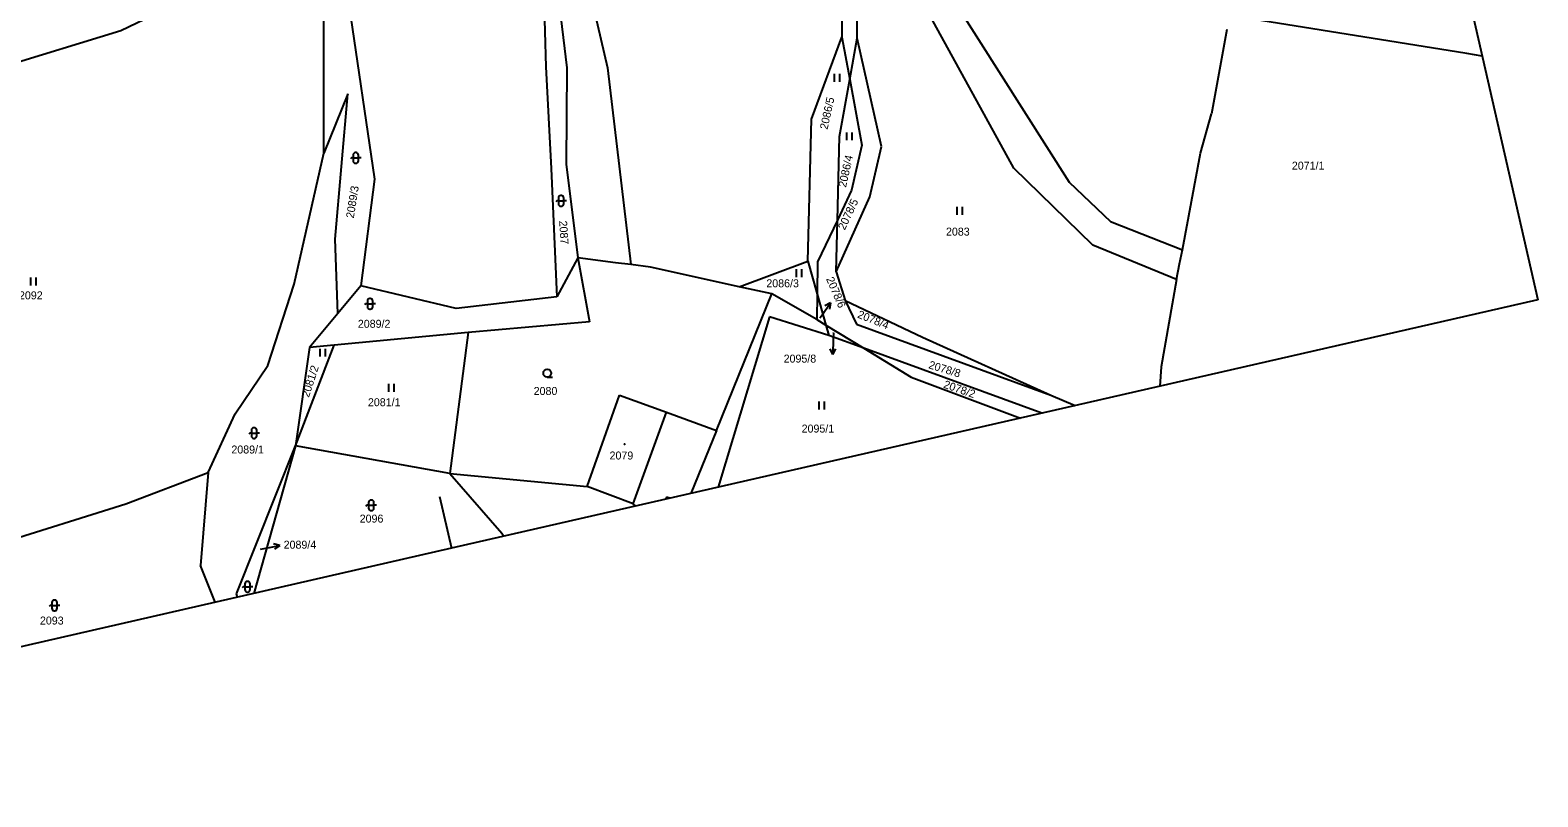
# Model space of a CAD drawing. Extents: x -805730 to -804640, y -1150889 to -1150366.
# Drawn here: x -804924.5 to -804640.4, y -1150749.1 to -1150604.7 of the extents above; entities that cross this region are included whole.
import ezdxf

# ---------------------------------------------------------------- set-up
doc = ezdxf.new("R2010")
doc.units = 0
for name, color, linetype in [('Default', 7, 'Continuous'), ('formát', 7, 'Continuous'), ('kn_celek - Cisla parcel pomocna', 7, 'Continuous'), ('kn_celek - Cisla pozemkovych parcel', 7, 'Continuous'), ('kn_celek - Cisla stavebnich parcel', 7, 'Continuous'), ('kn_celek - Hranice parcel', 7, 'Continuous'), ('kn_celek - Vnitrni kresby', 7, 'Continuous'), ('kn_celek - Znacky budov', 7, 'Continuous'), ('kn_celek - Znacky kultur', 7, 'Continuous')]:
    doc.layers.add(name, color=color, linetype=linetype)

# ---------------------------------------------------------------- blocks, each defined once
blk = doc.blocks.new('304')
at = {"layer": 'Default'}
blk.add_line((-0.1, 0), (9.9, 0), dxfattribs=at)
blk.add_circle((-0.1, 7.5), 7.5, dxfattribs=at)
blk = doc.blocks.new('306')
at = {"layer": 'Default'}
for p, q in [((-5.2, 0), (-5.2, 15)), ((4.8, 0), (4.8, 15))]:
    blk.add_line(p, q, dxfattribs=at)
blk = doc.blocks.new('316')
at = {"layer": 'Default'}
for p, q in [((-8.3, 10), (-10, 8.1)), ((-5, 10), (-8.3, 10)), ((-5, 15.5), (-5, 4.5)), ((-5, 10), (5, 10)), ((0.5, 20), (-0.5, 20)), ((-0.5, 0), (0.5, 0)), ((5, 4.5), (5, 15.5)), ((10, 10), (5, 10))]:
    blk.add_line(p, q, dxfattribs=at)
for centre, start, end in [((-0.5, 15.5), 90, 180), ((-0.5, 4.5), 180, 270), ((0.5, 15.5), 0, 90), ((0.5, 4.5), 270, 0)]:
    blk.add_arc(centre, 4.5, start, end, dxfattribs=at)
blk = doc.blocks.new('402')
at = {"layer": 'Default'}
for p, q in [((-0.8, 0.8), (0.7, 0.8)), ((-0.8, 0.8), (-0.8, -0.7)), ((0.7, 0.8), (0.7, -0.7)), ((0.7, -0.7), (-0.8, -0.7))]:
    blk.add_line(p, q, dxfattribs=at)
blk = doc.blocks.new('Z61')
at = {"layer": 'Default'}
for p, q in [((0, 0), (30, 0)), ((30, 0), (19.2, 5.3)), ((30, 0), (19.2, -5.3))]:
    blk.add_line(p, q, dxfattribs=at)

msp = doc.modelspace()

# ---------------------------------------------------------------- linework, layer by layer
at = {"layer": 'formát'}
for p, q in [((-804706.6, -1150365.97), (-804640.43, -1150655.5)), ((-804640.43, -1150655.5), (-804845.15, -1150702.29)), ((-804847.38, -1150692.54), (-804845.15, -1150702.29)), ((-804847.38, -1150692.54), (-804845.15, -1150702.29)), ((-804845.15, -1150702.29), (-805049.87, -1150749.08))]:
    msp.add_line(p, q, dxfattribs=at)
at = {"layer": 'kn_celek - Cisla parcel pomocna'}
for p, q in [((-804775.7, -1150658.91), (-804775.43, -1150658.53)), ((-804773.17, -1150661.74), (-804773.19, -1150662.83)), ((-804881.14, -1150702.45), (-804880.44, -1150702.32))]:
    msp.add_line(p, q, dxfattribs=at)
at = {"layer": 'kn_celek - Hranice parcel'}
for p, q in [((-804771.91, -1150579.38), (-804771.55, -1150606.03)), ((-804768.69, -1150606.23), (-804768.67, -1150582.3)), ((-804827.95, -1150589.7), (-804827.34, -1150611.64)), ((-804826.08, -1150589.72), (-804823.4, -1150611.86)), ((-804820.76, -1150589.98), (-804815.75, -1150611.81)), ((-804889.34, -1150596.17), (-804907.43, -1150604.85)), ((-804864.48, -1150599.92), (-804859.64, -1150632.81)), ((-804750.12, -1150599.8), (-804728.74, -1150633.39)), ((-804869.15, -1150627.88), (-804869.21, -1150602.7)), ((-804739.17, -1150630.73), (-804754.83, -1150602.27)), ((-804653.81, -1150609.12), (-804694.22, -1150602.66)), ((-804907.43, -1150604.85), (-804929.98, -1150611.77)), ((-804777.28, -1150621.47), (-804771.55, -1150606.03)), ((-804771.55, -1150606.03), (-804770.08, -1150614.03)), ((-804770.08, -1150614.03), (-804768.69, -1150606.23)), ((-804764.08, -1150626.66), (-804768.69, -1150606.23)), ((-804699.05, -1150604.64), (-804701.95, -1150620.52)), ((-804650.92, -1150609.61), (-804653.81, -1150609.12)), ((-804827.34, -1150611.64), (-804826.34, -1150630.79)), ((-804823.4, -1150611.86), (-804823.52, -1150629.98)), ((-804815.75, -1150611.81), (-804811.35, -1150648.88)), ((-804772, -1150624.77), (-804770.08, -1150614.03)), ((-804770.08, -1150614.03), (-804767.81, -1150626.42)), ((-804864.64, -1150616.76), (-804869.15, -1150627.88)), ((-804867.02, -1150644.1), (-804864.64, -1150616.76)), ((-804777.97, -1150648.22), (-804777.28, -1150621.47)), ((-804703.99, -1150627.92), (-804701.95, -1150620.52)), ((-804772.4, -1150640.49), (-804772, -1150624.77)), ((-804767.81, -1150626.42), (-804769.75, -1150634.89)), ((-804766.31, -1150636.13), (-804764.08, -1150626.66)), ((-804874.75, -1150652.58), (-804869.15, -1150627.88)), ((-804823.52, -1150629.98), (-804821.35, -1150647.6)), ((-804707.41, -1150646.12), (-804703.99, -1150627.92)), ((-804859.64, -1150632.81), (-804862.2, -1150652.87)), ((-804826.34, -1150630.79), (-804825.26, -1150654.97)), ((-804724.3, -1150645.21), (-804739.17, -1150630.73)), ((-804769.75, -1150634.89), (-804772.4, -1150640.49)), ((-804728.74, -1150633.39), (-804720.96, -1150640.79)), ((-804772.65, -1150650.27), (-804766.31, -1150636.13)), ((-804772.4, -1150640.49), (-804776.13, -1150648.36)), ((-804772.65, -1150650.27), (-804772.4, -1150640.49)), ((-804720.96, -1150640.79), (-804707.41, -1150646.12)), ((-804866.54, -1150658.07), (-804867.02, -1150644.1)), ((-804708.53, -1150651.71), (-804724.3, -1150645.21)), ((-804707.94, -1150648.75), (-804707.41, -1150646.12)), ((-804821.35, -1150647.6), (-804825.26, -1150654.97)), ((-804821.35, -1150647.6), (-804819.15, -1150659.64)), ((-804814.2, -1150648.52), (-804821.35, -1150647.6)), ((-804811.35, -1150648.88), (-804814.2, -1150648.52)), ((-804807.65, -1150649.35), (-804811.35, -1150648.88)), ((-804790.9, -1150653.05), (-804807.65, -1150649.35)), ((-804790.9, -1150653.05), (-804777.97, -1150648.22)), ((-804777.97, -1150648.22), (-804776.22, -1150654.42)), ((-804776.13, -1150648.36), (-804776.22, -1150654.42)), ((-804708.53, -1150651.71), (-804707.94, -1150648.75)), ((-804879.7, -1150667.88), (-804874.75, -1150652.58)), ((-804772.65, -1150650.27), (-804770.97, -1150655.66)), ((-804708.53, -1150651.71), (-804711.38, -1150668.12)), ((-804862.2, -1150652.87), (-804866.54, -1150658.07)), ((-804844.22, -1150657.16), (-804862.2, -1150652.87)), ((-804825.26, -1150654.97), (-804844.22, -1150657.16)), ((-804795.2, -1150680.11), (-804784.74, -1150654.41)), ((-804784.74, -1150654.41), (-804790.9, -1150653.05)), ((-804776.29, -1150659.21), (-804784.74, -1150654.41)), ((-804776.22, -1150654.42), (-804776.29, -1150659.21)), ((-804776.22, -1150654.42), (-804774.57, -1150660.26)), ((-804866.54, -1150658.07), (-804871.89, -1150664.5)), ((-804770.97, -1150655.66), (-804756.36, -1150662.51)), ((-804770.97, -1150655.66), (-804768.81, -1150660.09)), ((-804819.15, -1150659.64), (-804842, -1150661.64)), ((-804785.19, -1150658.73), (-804794.89, -1150690.8)), ((-804774.02, -1150662.2), (-804785.19, -1150658.73)), ((-804776.29, -1150659.21), (-804774.57, -1150660.26)), ((-804774.57, -1150660.26), (-804767.43, -1150664.63)), ((-804774.57, -1150660.26), (-804774.02, -1150662.2)), ((-804768.81, -1150660.09), (-804732.18, -1150673.45)), ((-804874.53, -1150683.02), (-804867.23, -1150664.05)), ((-804867.23, -1150664.05), (-804871.89, -1150664.5)), ((-804842, -1150661.64), (-804867.23, -1150664.05)), ((-804842, -1150661.64), (-804845.45, -1150688.21)), ((-804767.43, -1150664.63), (-804774.02, -1150662.2)), ((-804756.36, -1150662.51), (-804732.18, -1150673.45)), ((-804871.89, -1150664.5), (-804874.53, -1150683.02)), ((-804767.43, -1150664.63), (-804758.54, -1150670.07)), ((-804733.92, -1150676.87), (-804767.43, -1150664.63)), ((-804885.87, -1150676.95), (-804879.7, -1150667.88)), ((-804711.38, -1150668.12), (-804711.67, -1150671.78)), ((-804758.54, -1150670.07), (-804737.92, -1150677.78)), ((-804819.58, -1150690.67), (-804813.46, -1150673.44)), ((-804813.46, -1150673.44), (-804804.59, -1150676.68)), ((-804732.18, -1150673.45), (-804727.58, -1150675.42)), ((-804890.98, -1150688.02), (-804885.87, -1150676.95)), ((-804804.59, -1150676.68), (-804795.2, -1150680.11)), ((-804795.2, -1150680.11), (-804800.02, -1150691.98)), ((-804885.64, -1150710.87), (-804874.53, -1150683.02)), ((-804874.53, -1150683.02), (-804882.37, -1150710.79)), ((-804845.45, -1150688.21), (-804874.53, -1150683.02)), ((-804906.46, -1150693.95), (-804890.98, -1150688.02)), ((-804890.98, -1150688.02), (-804892.43, -1150705.53)), ((-804845.45, -1150688.21), (-804835.62, -1150699.43)), ((-804845.45, -1150688.21), (-804819.58, -1150690.67)), ((-804934.05, -1150702.55), (-804906.46, -1150693.95)), ((-804835.62, -1150699.43), (-804835.28, -1150700.03)), ((-804889.65, -1150712.46), (-804892.43, -1150705.53)), ((-804885.47, -1150711.5), (-804885.64, -1150710.87))]:
    msp.add_line(p, q, dxfattribs=at)
at = {"layer": 'kn_celek - Vnitrni kresby'}
for p, q in [((-804810.87, -1150693.89), (-804804.59, -1150676.68)), ((-804810.87, -1150693.89), (-804819.58, -1150690.67)), ((-804810.4, -1150694.35), (-804810.87, -1150693.89)), ((-804804.63, -1150692.65), (-804804.78, -1150693.06)), ((-804803.85, -1150692.85), (-804804.63, -1150692.65))]:
    msp.add_line(p, q, dxfattribs=at)

# ---------------------------------------------------------------- block references
at = {"layer": 'kn_celek - Cisla parcel pomocna'}
for p, xscale, yscale, rotation in [((-804775.43, -1150658.53), 0.1, 0.10000000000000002, 54.61578000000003), ((-804773.19, -1150662.83), 0.1, 0.09999999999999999, -91.12067999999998), ((-804880.44, -1150702.32), 0.10000000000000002, 0.10000000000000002, 10.885500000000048)]:
    msp.add_blockref('Z61', p, dxfattribs=dict(at, xscale=xscale, yscale=yscale, rotation=rotation))
at = {"layer": 'kn_celek - Znacky budov', "xscale": 0.1, "yscale": 0.10000000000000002}
msp.add_blockref('402', (-804812.54, -1150682.7), dxfattribs=at)
at = {"layer": 'kn_celek - Znacky kultur', "xscale": 0.1, "yscale": 0.10000000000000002}
for name, p in [('306', (-804772.44, -1150614.45)), ('306', (-804770.1, -1150625.48)), ('316', (-804863.16, -1150629.8)), ('316', (-804824.47, -1150637.89)), ('306', (-804749.35, -1150639.49)), ('306', (-804779.57, -1150651.27)), ('306', (-804923.88, -1150652.82)), ('316', (-804860.47, -1150657.27)), ('306', (-804869.37, -1150666.21)), ('304', (-804827.06, -1150670.07)), ('306', (-804856.39, -1150672.82)), ('306', (-804775.32, -1150676.13)), ('316', (-804882.32, -1150681.59)), ('316', (-804860.24, -1150695.2)), ('316', (-804883.56, -1150710.52)), ('316', (-804919.93, -1150714.04))]:
    msp.add_blockref(name, p, dxfattribs=at)

# ---------------------------------------------------------------- texts
at = {"layer": 'kn_celek - Cisla parcel pomocna'}
msp.add_text('2078/6', height=1.5, rotation=293.2945, dxfattribs=at).set_placement((-804774.57, -1150651.57))
for s, p in [('2095/8', (-804782.54, -1150667.33)), ('2089/4', (-804876.75, -1150702.36))]:
    msp.add_text(s, height=1.5, dxfattribs=at).set_placement(p)
at = {"layer": 'kn_celek - Cisla pozemkovych parcel'}
for s, rotation, p in [('2086/5', 77.5543, (-804774.28, -1150623.54)), ('2086/4', 77.4563, (-804770.8, -1150634.44)), ('2089/3', 81, (-804863.54, -1150640.23)), ('2078/5', 64.8617, (-804771.02, -1150642.49)), ('2087', 273.7294, (-804824.85, -1150640.66)), ('2078/4', 338.1213, (-804768.76, -1150658.82)), ('2081/2', 72, (-804872, -1150673.99)), ('2078/8', 343.0635, (-804755.34, -1150668.37)), ('2078/2', 340.915, (-804752.54, -1150672.03))]:
    msp.add_text(s, height=1.5, rotation=rotation, dxfattribs=at).set_placement(p)
for s, height, p in [('2071/1', 1.5, (-804686.78, -1150631)), ('2083', 1.5, (-804751.95, -1150643.42)), ('2086/3', 1.5, (-804785.8, -1150653.15)), ('2092', 1.5, (-804926.62, -1150655.42)), ('2089/2', 1.5, (-804862.77, -1150660.77)), ('2078/6', 0.1, (-804775.97, -1150658.88)), ('2095/8', 0.1, (-804773.45, -1150661.71)), ('2080', 1.5, (-804829.64, -1150673.42)), ('2081/1', 1.5, (-804860.87, -1150675.54)), ('2095/1', 1.5, (-804779.15, -1150680.5)), ('2089/1', 1.5, (-804886.6, -1150684.44)), ('2096', 1.5, (-804862.42, -1150697.45)), ('2089/4', 0.1, (-804881.14, -1150702.42)), ('2093', 1.5, (-804922.67, -1150716.64))]:
    msp.add_text(s, height=height, dxfattribs=at).set_placement(p)
at = {"layer": 'kn_celek - Cisla stavebnich parcel'}
msp.add_text('2079', height=1.5, dxfattribs=at).set_placement((-804815.34, -1150685.57))

doc.saveas('drawing.dxf')
